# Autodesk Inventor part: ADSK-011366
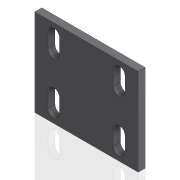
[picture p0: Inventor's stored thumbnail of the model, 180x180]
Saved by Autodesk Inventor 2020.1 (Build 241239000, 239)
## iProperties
Created: 1999-12
Part Number: ADSK-011366
Material: Acier doux
Document SubType Name: Modeling
Designer: sspink
Density: 7.86 g/cm^3
Appearance: Metal-Steel(Polish)
Mass: 283.235 g
Surface Area: 153.817 cm^2
Volume: 36.035 cm^3
Control State: 0
Checked Out: False
Master: False
Shininess: 0.0
Length Units: 11269
Angle Units: 11279
Time Units: 11290
Mass Units: 11283
Length Display Precision: 3
Angle Display Precision: 2
Compacted: True
Dimensions: 90x76x6 mm
Mass: 0,283 kg
DocNumber: ADSK-011366.ipt
Folder: 01 - Themengebiete\Simplification\01 - Packaging machine\
VDS_Category: 3D Komponenten
Density: 0.0
Volumn: 0.0
Area: 0.0
PropertySet Name: Model Information
Author: sspink
Revision Number: -
Title: base plate
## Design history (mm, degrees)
workpoint "Arbeitspunkt3"
workpoint "Arbeitspunkt4"
workpoint "Arbeitspunkt5"
workpoint "Arbeitspunkt6"
workaxis "Arbeitsachse3"
workaxis "Arbeitsachse4"
workaxis "Arbeitsachse5"
workaxis "Arbeitsachse6"
node "Extrusion2" dims "d8" = 6.35, "d9" = 0
  sketch "Sketch2"
    geometry: L1 (-45, -38)-(-45, 38) reference; L2 (-33.5, 16)-(-23.5, 16); L3 (-23.5, 16)-(-23.5, 29); L4 (-23.5, 29)-(-33.5, 29); L5 (-33.5, 29)-(-33.5, 16); L6 (-28.5, 16)-(-28.5, 29); A1 r 5 centre (-28.5, 29) between (-23.5, 29) and (-33.5, 29); A2 r 5 centre (-28.5, 16) between (-33.5, 16) and (-23.5, 16); 3 further points
    constraints: 10 end point, 4 point on circle, 2 centre point, 2 midpoint, 2 parallel, 2 tangent, 1 horizontal, 1 perpendicular, 1 vertical
    dimensions: "d4" = 13 distance of L2.end L3.end; "d5" = 5 radius of A2; "d20" = 22.5 vertical distance of point (-28.5, 22.5) point (-45, 0); "d21" = 28.5 horizontal distance of point (-28.5, 22.5) point (0, 0)
node "Rectangular Pattern1" dims "d10" = 20, "d12" = 57, "d13" = 20, "d15" = -45
node "Solide1"
  node "Extrusion1" dims "d2" = 6, "d3" = 0
sketch "Sketch1"
  geometry: L1 (-45, -38)-(45, -38); L2 (45, -38)-(45, 38); L3 (45, 38)-(-45, 38); L4 (-45, 38)-(-45, -38); 3 further points
  constraints: 8 end point, 2 midpoint, 2 parallel, 1 horizontal, 1 horizontal alignment, 1 perpendicular, 1 vertical alignment
  dimensions: "d0" = 90 distance between parallel lines of L2 L4; "d1" = 76 distance of L1.end L2.end
node "Corps solides"
node "Corps surfaciques"
